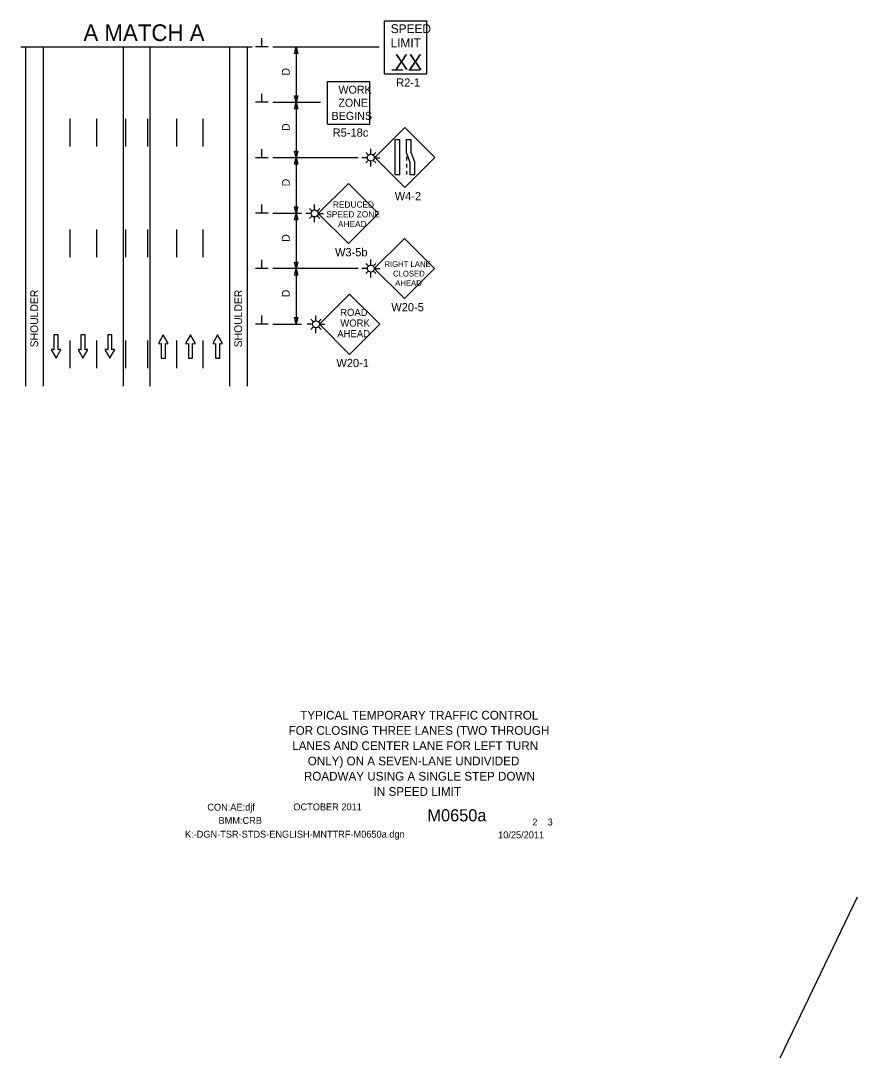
# Model space of a CAD drawing. Extents: x 16544 to 19504, y 5662 to 6909.
# Drawn here: x 17951 to 18706, y 5735 to 6671 of the extents above; entities that cross this region are included whole.
import ezdxf

# ---------------------------------------------------------------- set-up
doc = ezdxf.new("R2010")
doc.units = 0
for name, color, linetype in [('ALI_LEGAL_EX', 7, 'Continuous'), ('BORDER', 7, 'Continuous'), ('BORDER_SIGNAL_WO', 7, 'Continuous'), ('MT_SCRATCH_LEVEL_E', 7, 'Continuous'), ('PAVT_EDGE_EX', 7, 'Continuous'), ('TRAFFIC_SIGNS_PR', 7, 'Continuous'), ('TYPICAL_TEXT_DIMEN_PR', 7, 'Continuous')]:
    doc.layers.add(name, color=color, linetype=linetype)

msp = doc.modelspace()

# ---------------------------------------------------------------- linework, layer by layer
at = {"layer": 'ALI_LEGAL_EX'}
for points in [[(17995.77, 6582.18), (17995.77, 6557.18)], [(18019.77, 6582.18), (18019.77, 6557.18)], [(18045.77, 6582.18), (18045.77, 6557.18)], [(18065.77, 6582.18), (18065.77, 6557.18)], [(18091.77, 6582.18), (18091.77, 6557.18)], [(18115.77, 6582.18), (18115.77, 6557.18)], [(17995.77, 6482.18), (17995.77, 6457.18)], [(18019.77, 6482.18), (18019.77, 6457.18)], [(18045.77, 6482.18), (18045.77, 6457.18)], [(18065.77, 6482.18), (18065.77, 6457.18)], [(18091.77, 6482.18), (18091.77, 6457.18)], [(18115.77, 6482.18), (18115.77, 6457.18)], [(17995.77, 6382.18), (17995.77, 6357.18)], [(18019.77, 6382.18), (18019.77, 6357.18)], [(18045.77, 6382.18), (18045.77, 6357.18)], [(18065.77, 6382.18), (18065.77, 6357.18)], [(18091.77, 6382.18), (18091.77, 6357.18)], [(18115.77, 6382.18), (18115.77, 6357.18)]]:
    msp.add_lwpolyline(points, dxfattribs=at)
at = {"layer": 'BORDER'}
msp.add_line((18318.25, 6011.25), (18318.25, 6011.25), dxfattribs=at)
at = {"layer": 'MT_SCRATCH_LEVEL_E'}
for p, q in [((17985.18, 6387.14), (17981.44, 6387.14)), ((17981.44, 6387.14), (17981.44, 6373.88)), ((17985.18, 6387.14), (17981.44, 6387.14)), ((17981.44, 6387.14), (17981.44, 6373.88)), ((17985.18, 6373.88), (17985.18, 6387.14)), ((17985.18, 6373.88), (17985.18, 6387.14)), ((18009.44, 6387.14), (18005.69, 6387.14)), ((18005.69, 6387.14), (18005.69, 6373.88)), ((18009.44, 6387.14), (18005.69, 6387.14)), ((18005.69, 6387.14), (18005.69, 6373.88)), ((18009.44, 6373.88), (18009.44, 6387.14)), ((18009.44, 6373.88), (18009.44, 6387.14)), ((18033.69, 6387.14), (18029.95, 6387.14)), ((18029.95, 6387.14), (18029.95, 6373.88)), ((18033.69, 6387.14), (18029.95, 6387.14)), ((18029.95, 6387.14), (18029.95, 6373.88)), ((18033.69, 6373.88), (18033.69, 6387.14)), ((18033.69, 6373.88), (18033.69, 6387.14)), ((18080.01, 6387.14), (18075.9, 6379.9)), ((18080.01, 6387.14), (18075.9, 6379.9)), ((18084.16, 6379.9), (18080.01, 6387.14)), ((18084.16, 6379.9), (18080.01, 6387.14)), ((18104.51, 6387.14), (18100.4, 6379.9)), ((18104.51, 6387.14), (18100.4, 6379.9)), ((18108.65, 6379.9), (18104.51, 6387.14)), ((18108.65, 6379.9), (18104.51, 6387.14)), ((18129, 6387.14), (18124.89, 6379.9)), ((18129, 6387.14), (18124.89, 6379.9)), ((18133.15, 6379.9), (18129, 6387.14)), ((18133.15, 6379.9), (18129, 6387.14)), ((17979.18, 6373.51), (17983.33, 6366.27)), ((17979.18, 6373.51), (17983.33, 6366.27)), ((17981.44, 6373.88), (17979.66, 6374.2)), ((17981.44, 6373.88), (17979.66, 6374.2)), ((17983.33, 6366.27), (17987.44, 6373.51)), ((17983.33, 6366.27), (17987.44, 6373.51)), ((17986.96, 6374.2), (17985.18, 6373.88)), ((17986.96, 6374.2), (17985.18, 6373.88)), ((18003.44, 6373.51), (18007.58, 6366.27)), ((18003.44, 6373.51), (18007.58, 6366.27)), ((18005.69, 6373.88), (18003.92, 6374.2)), ((18005.69, 6373.88), (18003.92, 6374.2)), ((18007.58, 6366.27), (18011.69, 6373.51)), ((18007.58, 6366.27), (18011.69, 6373.51)), ((18011.21, 6374.2), (18009.44, 6373.88)), ((18011.21, 6374.2), (18009.44, 6373.88)), ((18027.69, 6373.51), (18031.84, 6366.27)), ((18027.69, 6373.51), (18031.84, 6366.27)), ((18029.95, 6373.88), (18028.17, 6374.2)), ((18029.95, 6373.88), (18028.17, 6374.2)), ((18031.84, 6366.27), (18035.95, 6373.51)), ((18031.84, 6366.27), (18035.95, 6373.51)), ((18035.47, 6374.2), (18033.69, 6373.88)), ((18035.47, 6374.2), (18033.69, 6373.88)), ((18076.38, 6379.22), (18078.16, 6379.53)), ((18076.38, 6379.22), (18078.16, 6379.53)), ((18078.16, 6379.53), (18078.16, 6366.27)), ((18078.16, 6379.53), (18078.16, 6366.27)), ((18081.9, 6366.27), (18081.9, 6379.53)), ((18081.9, 6379.53), (18083.68, 6379.22)), ((18081.9, 6366.27), (18081.9, 6379.53)), ((18081.9, 6379.53), (18083.68, 6379.22)), ((18100.88, 6379.22), (18102.65, 6379.53)), ((18100.88, 6379.22), (18102.65, 6379.53)), ((18102.65, 6379.53), (18102.65, 6366.27)), ((18102.65, 6379.53), (18102.65, 6366.27)), ((18106.4, 6366.27), (18106.4, 6379.53)), ((18106.4, 6379.53), (18108.17, 6379.22)), ((18106.4, 6366.27), (18106.4, 6379.53)), ((18106.4, 6379.53), (18108.17, 6379.22)), ((18125.37, 6379.22), (18127.15, 6379.53)), ((18125.37, 6379.22), (18127.15, 6379.53)), ((18127.15, 6379.53), (18127.15, 6366.27)), ((18127.15, 6379.53), (18127.15, 6366.27)), ((18130.89, 6366.27), (18130.89, 6379.53)), ((18130.89, 6379.53), (18132.67, 6379.22)), ((18130.89, 6366.27), (18130.89, 6379.53)), ((18130.89, 6379.53), (18132.67, 6379.22)), ((18078.16, 6366.27), (18081.9, 6366.27)), ((18078.16, 6366.27), (18081.9, 6366.27)), ((18102.65, 6366.27), (18106.4, 6366.27)), ((18102.65, 6366.27), (18106.4, 6366.27)), ((18127.15, 6366.27), (18130.89, 6366.27)), ((18127.15, 6366.27), (18130.89, 6366.27))]:
    msp.add_line(p, q, dxfattribs=at)
for centre, start, end in [((17979.59, 6373.74), 80.03619, 209.77312), ((17979.59, 6373.74), 80.03619, 209.77312), ((17987.03, 6373.74), 330.42484, 99.96381), ((17987.03, 6373.74), 330.42484, 99.96381), ((18003.85, 6373.74), 80.03619, 209.77312), ((18003.85, 6373.74), 80.03619, 209.77312), ((18011.29, 6373.74), 330.42484, 99.96381), ((18011.29, 6373.74), 330.42484, 99.96381), ((18028.1, 6373.74), 80.03619, 209.77312), ((18028.1, 6373.74), 80.03619, 209.77312), ((18035.54, 6373.74), 330.42484, 99.96381), ((18035.54, 6373.74), 330.42484, 99.96381), ((18076.31, 6379.67), 150.42484, 279.96381), ((18076.31, 6379.67), 150.42484, 279.96381), ((18083.75, 6379.67), 260.03619, 29.77312), ((18083.75, 6379.67), 260.03619, 29.77312), ((18100.8, 6379.67), 150.42484, 279.96381), ((18100.8, 6379.67), 150.42484, 279.96381), ((18108.24, 6379.67), 260.03619, 29.77312), ((18108.24, 6379.67), 260.03619, 29.77312), ((18125.3, 6379.67), 150.42484, 279.96381), ((18125.3, 6379.67), 150.42484, 279.96381), ((18132.74, 6379.67), 260.03619, 29.77312), ((18132.74, 6379.67), 260.03619, 29.77312)]:
    msp.add_arc(centre, 0.463, start, end, dxfattribs=at)
at = {"layer": 'PAVT_EDGE_EX'}
for p, q in [((17955.77, 6647.01), (17955.77, 6340.84)), ((17971.77, 6647.01), (17971.77, 6340.84)), ((18043.77, 6647.01), (18043.77, 6340.84)), ((18067.77, 6647.01), (18067.77, 6340.84)), ((18139.77, 6647.01), (18139.77, 6340.84)), ((18155.77, 6647.01), (18155.77, 6340.84))]:
    msp.add_line(p, q, dxfattribs=at)
at = {"layer": 'TRAFFIC_SIGNS_PR'}
for p, q in [((18279.35, 6670.59), (18317.75, 6670.59)), ((18279.35, 6622.59), (18279.35, 6670.59)), ((18279.35, 6670.59), (18317.75, 6670.59)), ((18279.35, 6622.59), (18279.35, 6670.59)), ((18317.75, 6622.59), (18317.75, 6670.59)), ((18317.75, 6622.59), (18317.75, 6670.59)), ((18285.99, 6626.23), (18296.05, 6626.23)), ((18301.43, 6626.23), (18311.49, 6626.23)), ((18279.35, 6622.59), (18317.75, 6622.59)), ((18279.35, 6622.59), (18317.75, 6622.59)), ((18227.95, 6577.43), (18227.95, 6615.83)), ((18227.95, 6615.83), (18266.35, 6615.83)), ((18266.35, 6577.43), (18266.35, 6615.83)), ((18227.95, 6577.43), (18266.35, 6577.43)), ((18297.76, 6574.44), (18270.61, 6547.29)), ((18324.92, 6547.29), (18297.76, 6574.44)), ((18264.62, 6549.58), (18262.52, 6551.69)), ((18267.14, 6550.62), (18267.14, 6555.12)), ((18269.65, 6549.58), (18271.76, 6551.69)), ((18263.98, 6547.06), (18259.15, 6547.06)), ((18264.62, 6544.55), (18262.52, 6542.44)), ((18267.14, 6539.1), (18267.14, 6543.51)), ((18269.65, 6544.55), (18271.76, 6542.44)), ((18270.29, 6547.06), (18275.17, 6547.06)), ((18270.61, 6547.29), (18297.76, 6520.14)), ((18297.76, 6520.14), (18324.92, 6547.29)), ((18299.4, 6547.78), (18299.4, 6544.58)), ((18299.4, 6541.38), (18299.4, 6538.18)), ((18299.4, 6534.98), (18299.4, 6531.78)), ((18246.91, 6523.84), (18219.75, 6496.68)), ((18274.06, 6496.68), (18246.91, 6523.84)), ((18216.42, 6500.29), (18216.42, 6504.79)), ((18213.26, 6496.73), (18208.43, 6496.73)), ((18213.9, 6499.25), (18211.8, 6501.35)), ((18218.93, 6499.25), (18221.04, 6501.35)), ((18219.57, 6496.73), (18224.45, 6496.73)), ((18219.75, 6496.68), (18246.91, 6469.53)), ((18246.91, 6469.53), (18274.06, 6496.68)), ((18213.9, 6494.22), (18211.8, 6492.11)), ((18216.42, 6488.77), (18216.42, 6493.18)), ((18218.93, 6494.22), (18221.04, 6492.11)), ((18297.44, 6474.24), (18270.29, 6447.09)), ((18324.6, 6447.09), (18297.44, 6474.24)), ((18264.62, 6449.61), (18262.52, 6451.71)), ((18267.14, 6450.65), (18267.14, 6455.15)), ((18269.65, 6449.61), (18271.76, 6451.71)), ((18263.98, 6447.09), (18259.15, 6447.09)), ((18264.62, 6444.58), (18262.52, 6442.47)), ((18267.14, 6439.13), (18267.14, 6443.54)), ((18269.65, 6444.58), (18271.76, 6442.47)), ((18270.29, 6447.09), (18275.17, 6447.09)), ((18270.29, 6447.09), (18297.44, 6419.94)), ((18297.44, 6419.94), (18324.6, 6447.09)), ((18247.95, 6423.95), (18220.76, 6396.76)), ((18275.13, 6396.76), (18247.95, 6423.95)), ((18217.6, 6400.32), (18217.6, 6404.82)), ((18214.45, 6396.76), (18209.62, 6396.76)), ((18215.09, 6399.28), (18212.99, 6401.39)), ((18215.09, 6394.25), (18212.99, 6392.14)), ((18217.6, 6388.8), (18217.6, 6393.21)), ((18220.12, 6399.28), (18222.23, 6401.39)), ((18220.12, 6394.25), (18222.23, 6392.14)), ((18220.76, 6396.76), (18225.64, 6396.76)), ((18220.76, 6396.76), (18247.95, 6369.58)), ((18247.95, 6369.58), (18275.13, 6396.76))]:
    msp.add_line(p, q, dxfattribs=at)
for points in [[(18288.87, 6563.03), (18288.87, 6531.78), (18293.36, 6531.78), (18293.36, 6563.03)], [(18299, 6563.03), (18299, 6551.84), (18302.35, 6542.96), (18302.35, 6531.78), (18306.84, 6531.78), (18306.84, 6542.96), (18303.5, 6551.84), (18303.5, 6563.03)]]:
    msp.add_lwpolyline(points, close=True, dxfattribs=at)
for centre in [(18267.14, 6547.06), (18216.42, 6496.73), (18267.14, 6447.09), (18217.61, 6396.76)]:
    msp.add_circle(centre, 3.15, dxfattribs=at)
at = {"layer": 'TYPICAL_TEXT_DIMEN_PR'}
for p, q in [((18168.89, 6647.01), (18168.89, 6654.79)), ((17951.47, 6647.01), (18160.07, 6647.01)), ((18043.77, 6647.01), (18067.77, 6647.01)), ((18174.52, 6647.01), (18163.27, 6647.01)), ((18178.77, 6647.01), (18274.55, 6647.01)), ((18198.2, 6641.15), (18199.77, 6647.01)), ((18199.77, 6647.01), (18201.34, 6641.15)), ((18199.77, 6647.01), (18199.77, 6597.01)), ((18199.77, 6641.15), (18198.2, 6641.15)), ((18201.34, 6641.15), (18199.77, 6641.15)), ((18168.89, 6597.01), (18168.89, 6604.79)), ((18199.77, 6597.01), (18198.2, 6602.87)), ((18198.2, 6602.87), (18199.77, 6602.87)), ((18199.77, 6602.87), (18201.34, 6602.87)), ((18201.34, 6602.87), (18199.77, 6597.01)), ((18174.52, 6597.01), (18163.27, 6597.01)), ((18178.77, 6597.01), (18221.64, 6597.01)), ((18198.2, 6591.15), (18199.77, 6597.01)), ((18199.77, 6591.15), (18198.2, 6591.15)), ((18199.77, 6597.01), (18201.34, 6591.15)), ((18199.77, 6597.01), (18199.77, 6547.01)), ((18201.34, 6591.15), (18199.77, 6591.15)), ((18168.89, 6547.01), (18168.89, 6554.79)), ((18199.77, 6547.01), (18198.2, 6552.87)), ((18198.2, 6552.87), (18199.77, 6552.87)), ((18199.77, 6552.87), (18201.34, 6552.87)), ((18201.34, 6552.87), (18199.77, 6547.01)), ((18174.52, 6547.01), (18163.27, 6547.01)), ((18255.57, 6547.01), (18178.77, 6547.01)), ((18198.2, 6541.15), (18199.77, 6547.01)), ((18199.77, 6547.01), (18201.34, 6541.15)), ((18199.77, 6547.01), (18199.77, 6497.01)), ((18199.77, 6541.15), (18198.2, 6541.15)), ((18201.34, 6541.15), (18199.77, 6541.15)), ((18168.89, 6497.01), (18168.89, 6504.79)), ((18174.52, 6497.01), (18163.27, 6497.01)), ((18178.77, 6497.01), (18204.77, 6497.01)), ((18199.77, 6497.01), (18198.2, 6502.87)), ((18198.2, 6502.87), (18199.77, 6502.87)), ((18198.2, 6491.15), (18199.77, 6497.01)), ((18199.77, 6502.87), (18201.34, 6502.87)), ((18201.34, 6502.87), (18199.77, 6497.01)), ((18199.77, 6497.01), (18201.34, 6491.15)), ((18199.77, 6497.01), (18199.77, 6447.01)), ((18199.77, 6491.15), (18198.2, 6491.15)), ((18201.34, 6491.15), (18199.77, 6491.15)), ((18168.89, 6447.01), (18168.89, 6454.79)), ((18199.77, 6447.01), (18198.2, 6452.87)), ((18198.2, 6452.87), (18199.77, 6452.87)), ((18199.77, 6452.87), (18201.34, 6452.87)), ((18201.34, 6452.87), (18199.77, 6447.01)), ((18174.52, 6447.01), (18163.27, 6447.01)), ((18255.57, 6447.01), (18178.77, 6447.01)), ((18198.2, 6441.15), (18199.77, 6447.01)), ((18199.77, 6441.15), (18198.2, 6441.15)), ((18199.77, 6447.01), (18201.34, 6441.15)), ((18199.77, 6447.01), (18199.77, 6397.01)), ((18201.34, 6441.15), (18199.77, 6441.15)), ((18168.89, 6397.01), (18168.89, 6404.79)), ((18199.77, 6397.01), (18198.2, 6402.87)), ((18198.2, 6402.87), (18199.77, 6402.87)), ((18199.77, 6402.87), (18201.34, 6402.87)), ((18201.34, 6402.87), (18199.77, 6397.01)), ((18174.52, 6397.01), (18163.27, 6397.01)), ((18178.77, 6397.01), (18204.77, 6397.01)), ((18705.75, 5880), (18635.9, 5734.7))]:
    msp.add_line(p, q, dxfattribs=at)

# ---------------------------------------------------------------- texts
at = {"layer": 'BORDER'}
for s, p in [('TYPICAL TEMPORARY TRAFFIC CONTROL', (18203.45, 6040.22)), ('FOR CLOSING THREE LANES (TWO THROUGH', (18192.95, 6026.46)), ('LANES AND CENTER LANE FOR LEFT TURN', (18196.28, 6012.7)), ('ONLY) ON A SEVEN-LANE UNDIVIDED', (18210.26, 5998.93)), ('ROADWAY USING A SINGLE STEP DOWN', (18206.78, 5985.17)), ('IN SPEED LIMIT', (18269.66, 5971.41))]:
    msp.add_text(s, height=7.8528, dxfattribs=at).set_placement(p)
at = {"layer": 'BORDER_SIGNAL_WO'}
for s, height, p in [('CON:AE:djf', 6.2, (18119.69, 5958.06)), ('    OCTOBER 2011    ', 6.2, (18188.08, 5958.34)), ('BMM:CRB   ', 6.2, (18129.81, 5946.17)), ('    M0650a   ', 11, (18301.86, 5948.38)), (' 2    3 ', 6.2, (18410.45, 5944.7)), ('K:-DGN-TSR-STDS-ENGLISH-MNTTRF-M0650a.dgn        ', 6.2, (18099.55, 5933.71)), ('10/25/2011    ', 6.2, (18381.93, 5933.13))]:
    msp.add_text(s, height=height, dxfattribs=at).set_placement(p)
at = {"layer": 'TRAFFIC_SIGNS_PR'}
for s, height, p in [('SPEED', 8, (18285.11, 6659.45)), ('SPEED', 8, (18285.11, 6659.45)), ('LIMIT', 8, (18284.95, 6646.65)), ('LIMIT', 8, (18284.95, 6646.65)), ('XX', 14.031, (18288.46, 6626.34)), ('R2-1', 7.44, (18290.02, 6611.15)), ('R2-1', 7.44, (18290.02, 6611.15)), ('WORK', 7.217, (18237.95, 6604.8)), ('ZONE', 7.217, (18237.83, 6592.99)), ('BEGINS', 7.217, (18231.76, 6581.18)), ('R5-18c', 7.44, (18232.76, 6565.99)), ('W4-2', 7.44, (18288.72, 6508.7)), ('REDUCED', 5.6, (18232.96, 6501.99)), ('SPEED ZONE', 5.6, (18226.96, 6493.19)), ('AHEAD', 5.6, (18237.52, 6484.39)), ('W3-5b', 7.44, (18234.86, 6458.09)), ('RIGHT LANE', 5.2, (18279.36, 6448.49)), ('CLOSED', 5.2, (18287.16, 6439.89)), ('AHEAD', 5.2, (18289.1, 6431.29)), ('W20-5', 7.44, (18285.62, 6408.5)), ('ROAD', 6.408, (18239.48, 6404.31)), ('WORK', 6.408, (18239.59, 6394.7)), ('AHEAD', 6.408, (18236.89, 6385.08)), ('W20-1', 7.449, (18236.1, 6358.12))]:
    msp.add_text(s, height=height, dxfattribs=at).set_placement(p)
at = {"layer": 'TYPICAL_TEXT_DIMEN_PR'}
msp.add_text('A MATCH A', height=15, dxfattribs=at).set_placement((18007.97, 6652.33))
for s, p in [('D', (18193.99, 6621.23)), ('D', (18193.99, 6571.23)), ('D', (18193.99, 6521.23)), ('D', (18193.99, 6471.23)), ('SHOULDER', (17967.14, 6375.99)), ('SHOULDER', (18151.05, 6375.99)), ('D', (18193.99, 6421.23))]:
    msp.add_text(s, height=7, rotation=90, dxfattribs=at).set_placement(p)

doc.saveas('drawing.dxf')
